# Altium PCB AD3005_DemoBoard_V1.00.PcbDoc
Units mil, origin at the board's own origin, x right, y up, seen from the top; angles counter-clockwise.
Board outline 3850.97 x 3540.97 mil, 2 copper layers (Top Layer, Bottom Layer); 155 components, 117 nets, 557 pads, 56 vias.
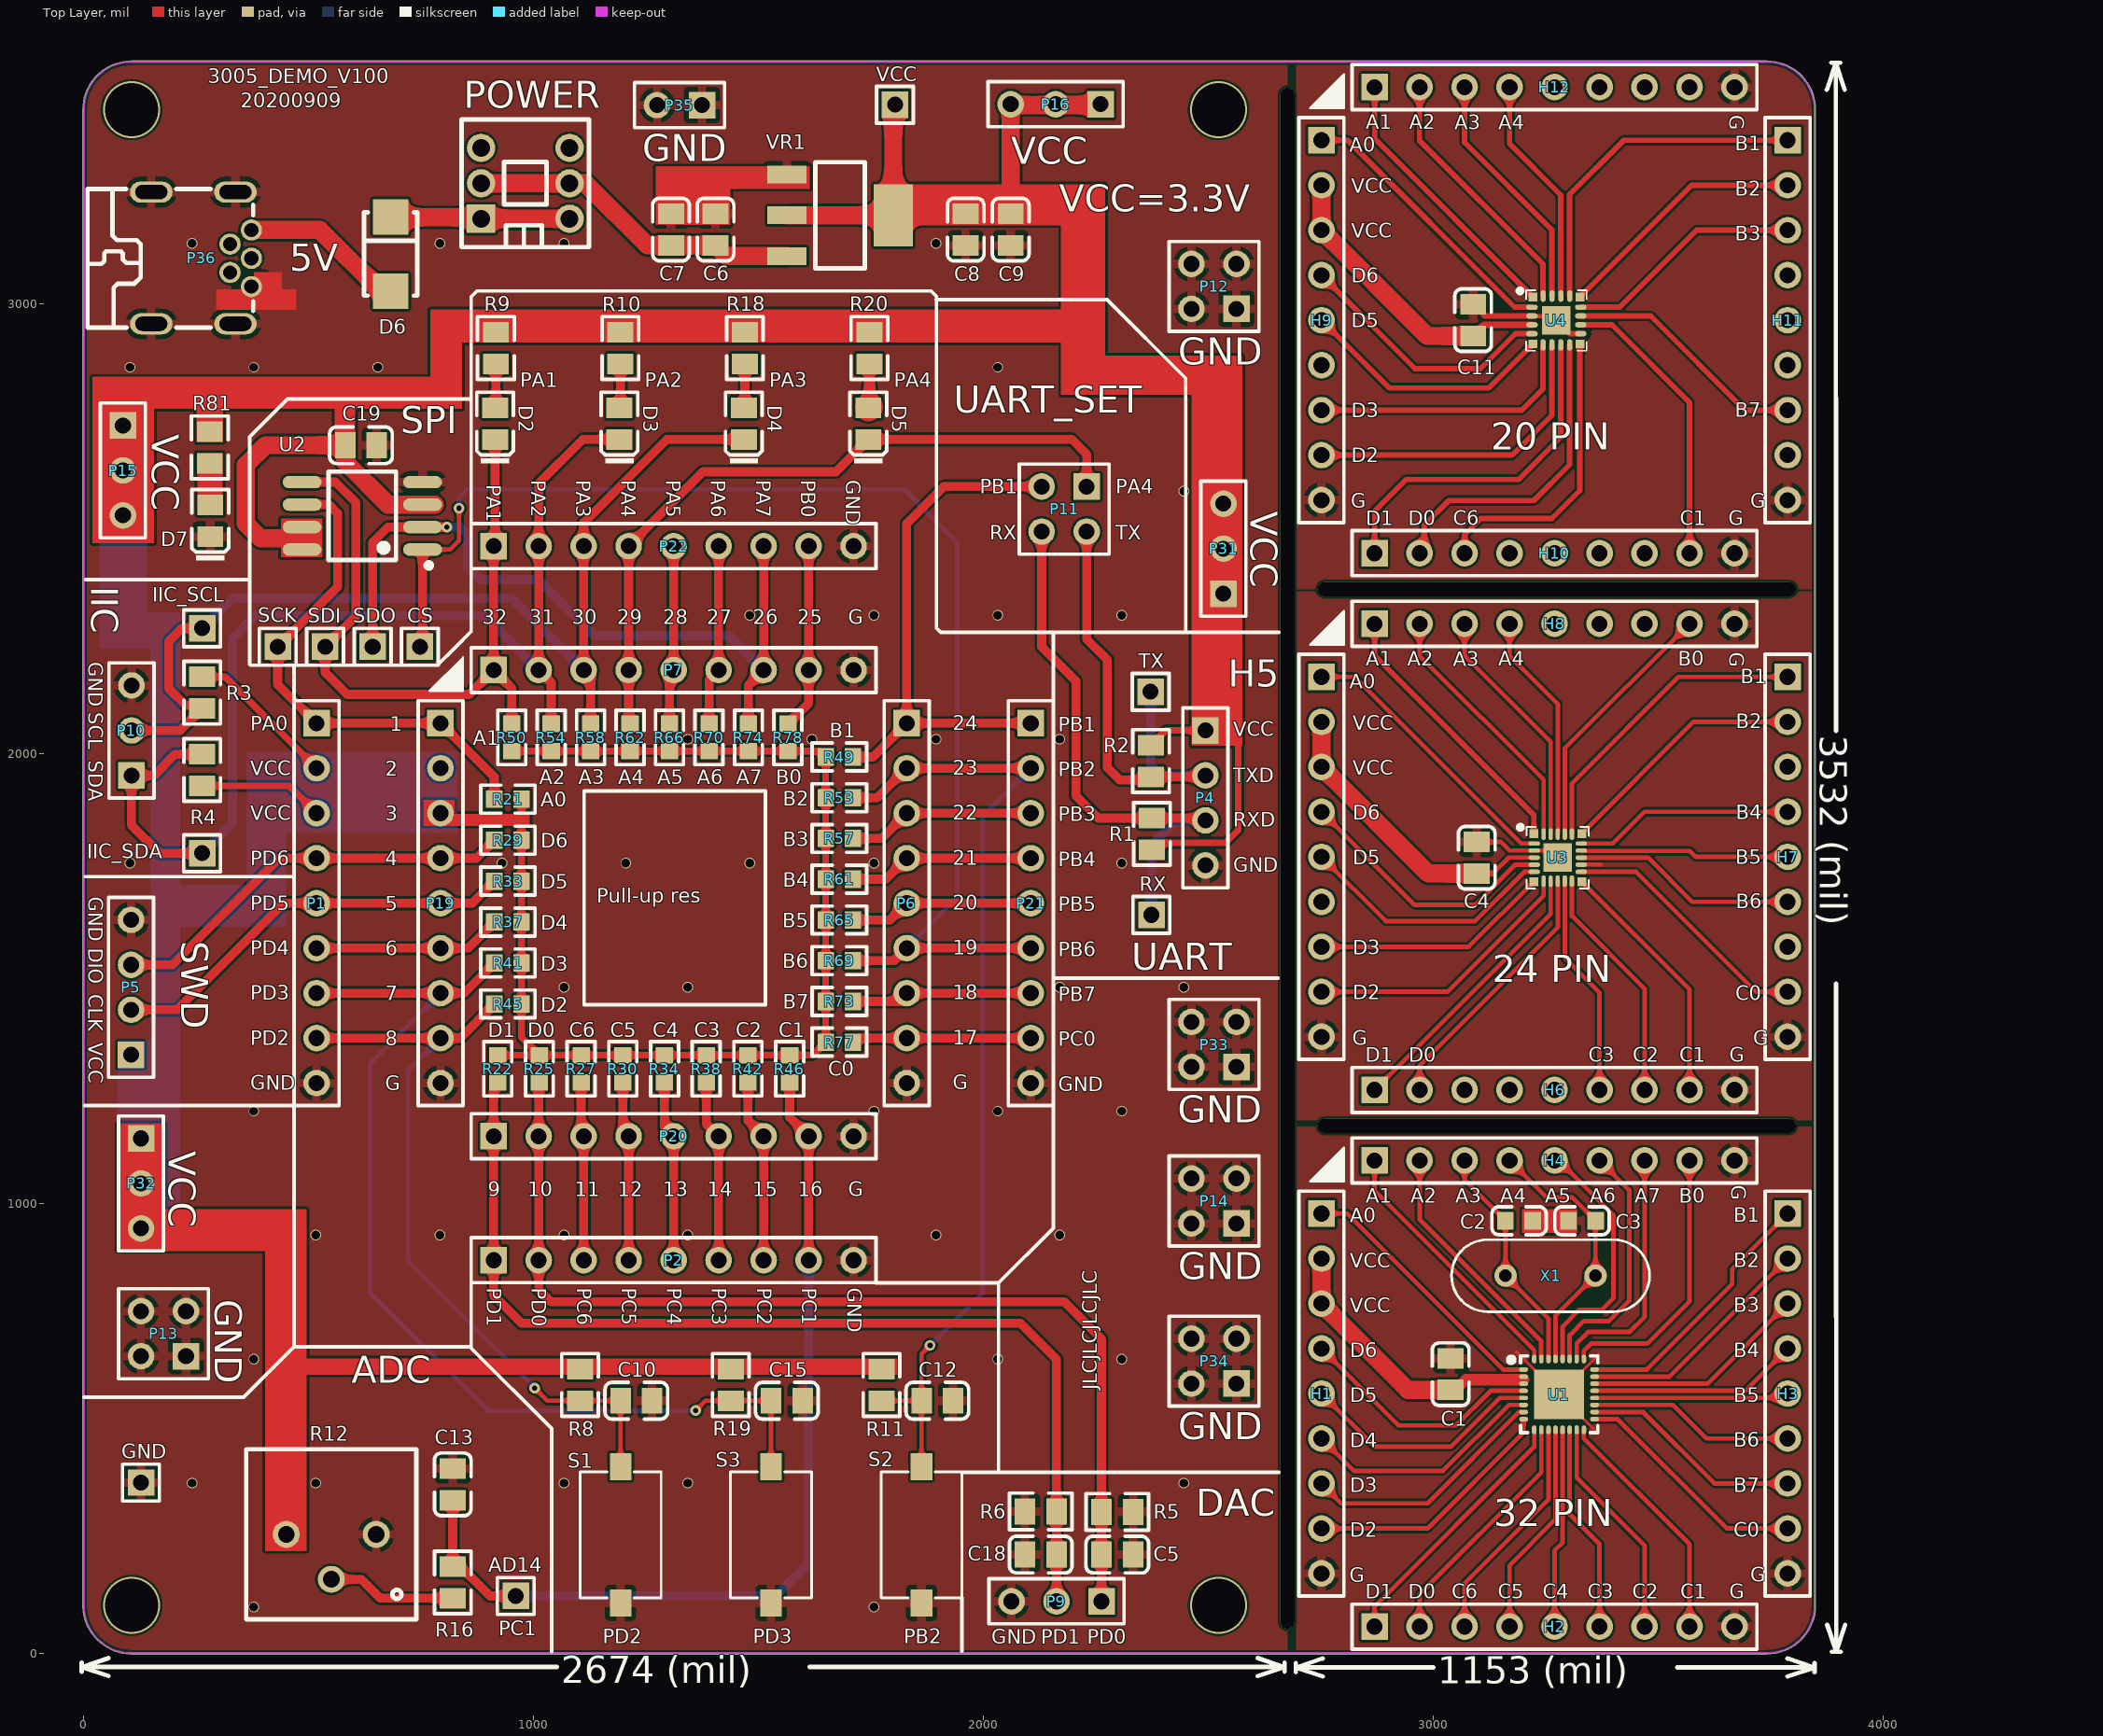
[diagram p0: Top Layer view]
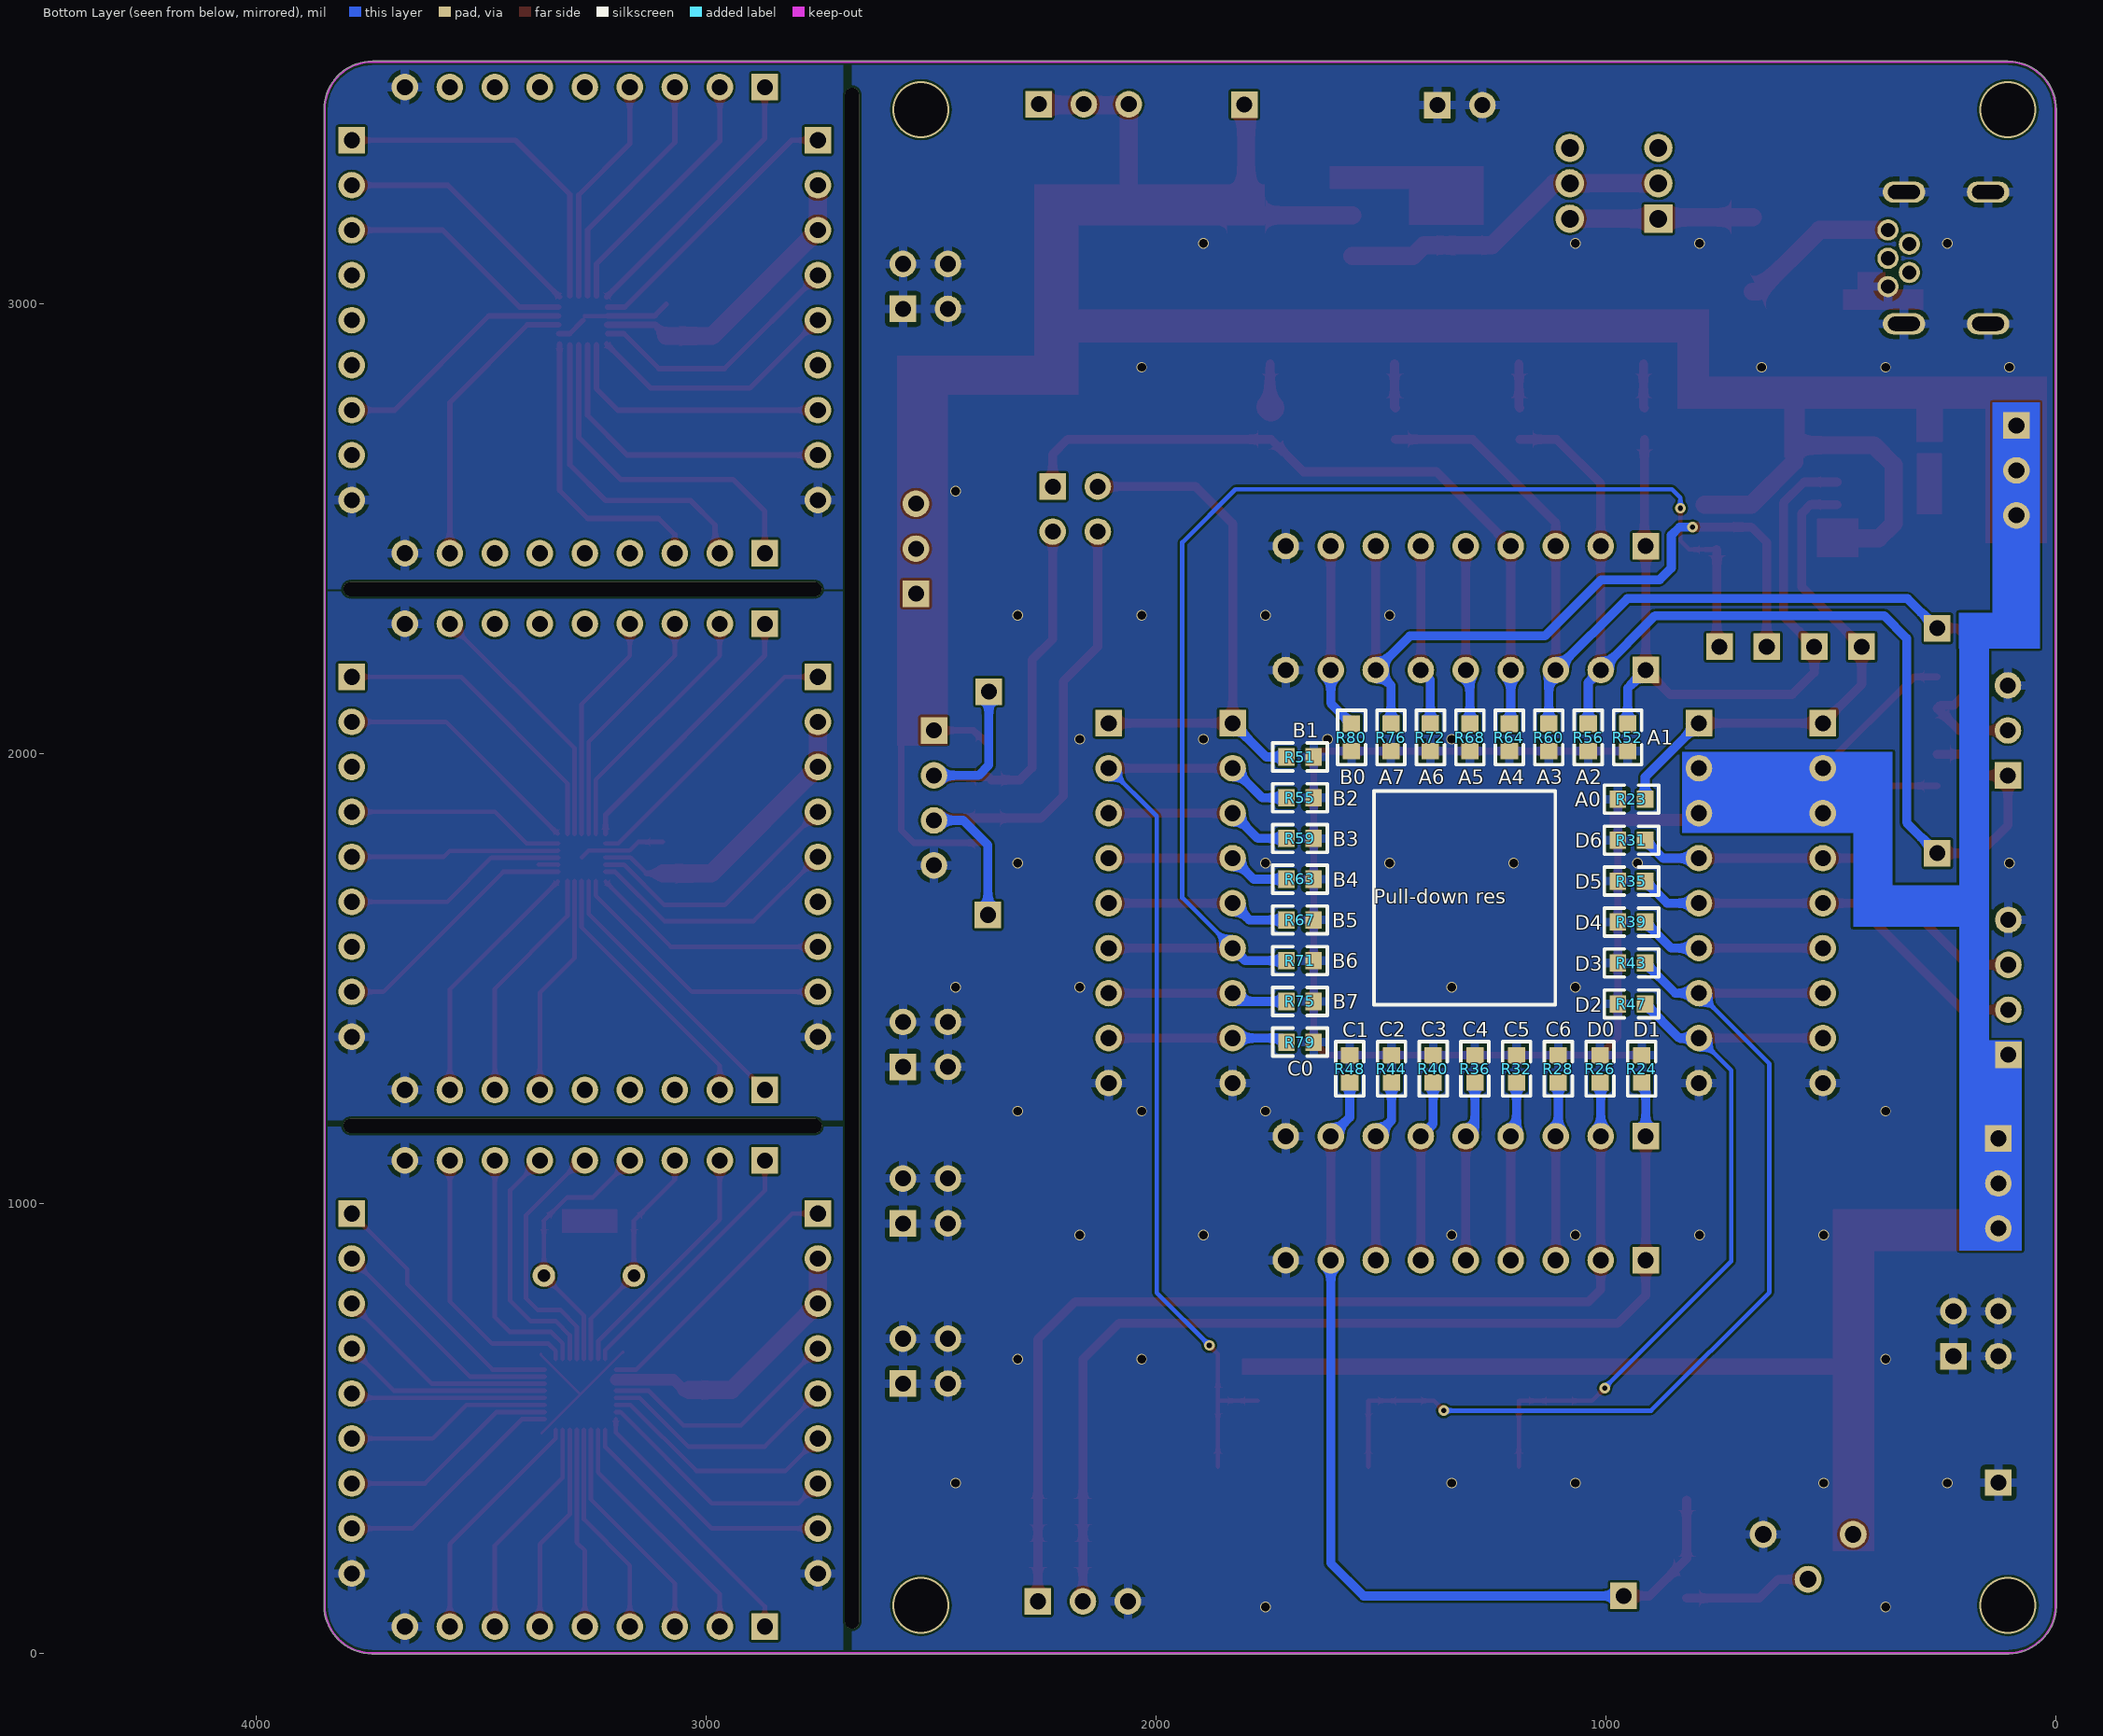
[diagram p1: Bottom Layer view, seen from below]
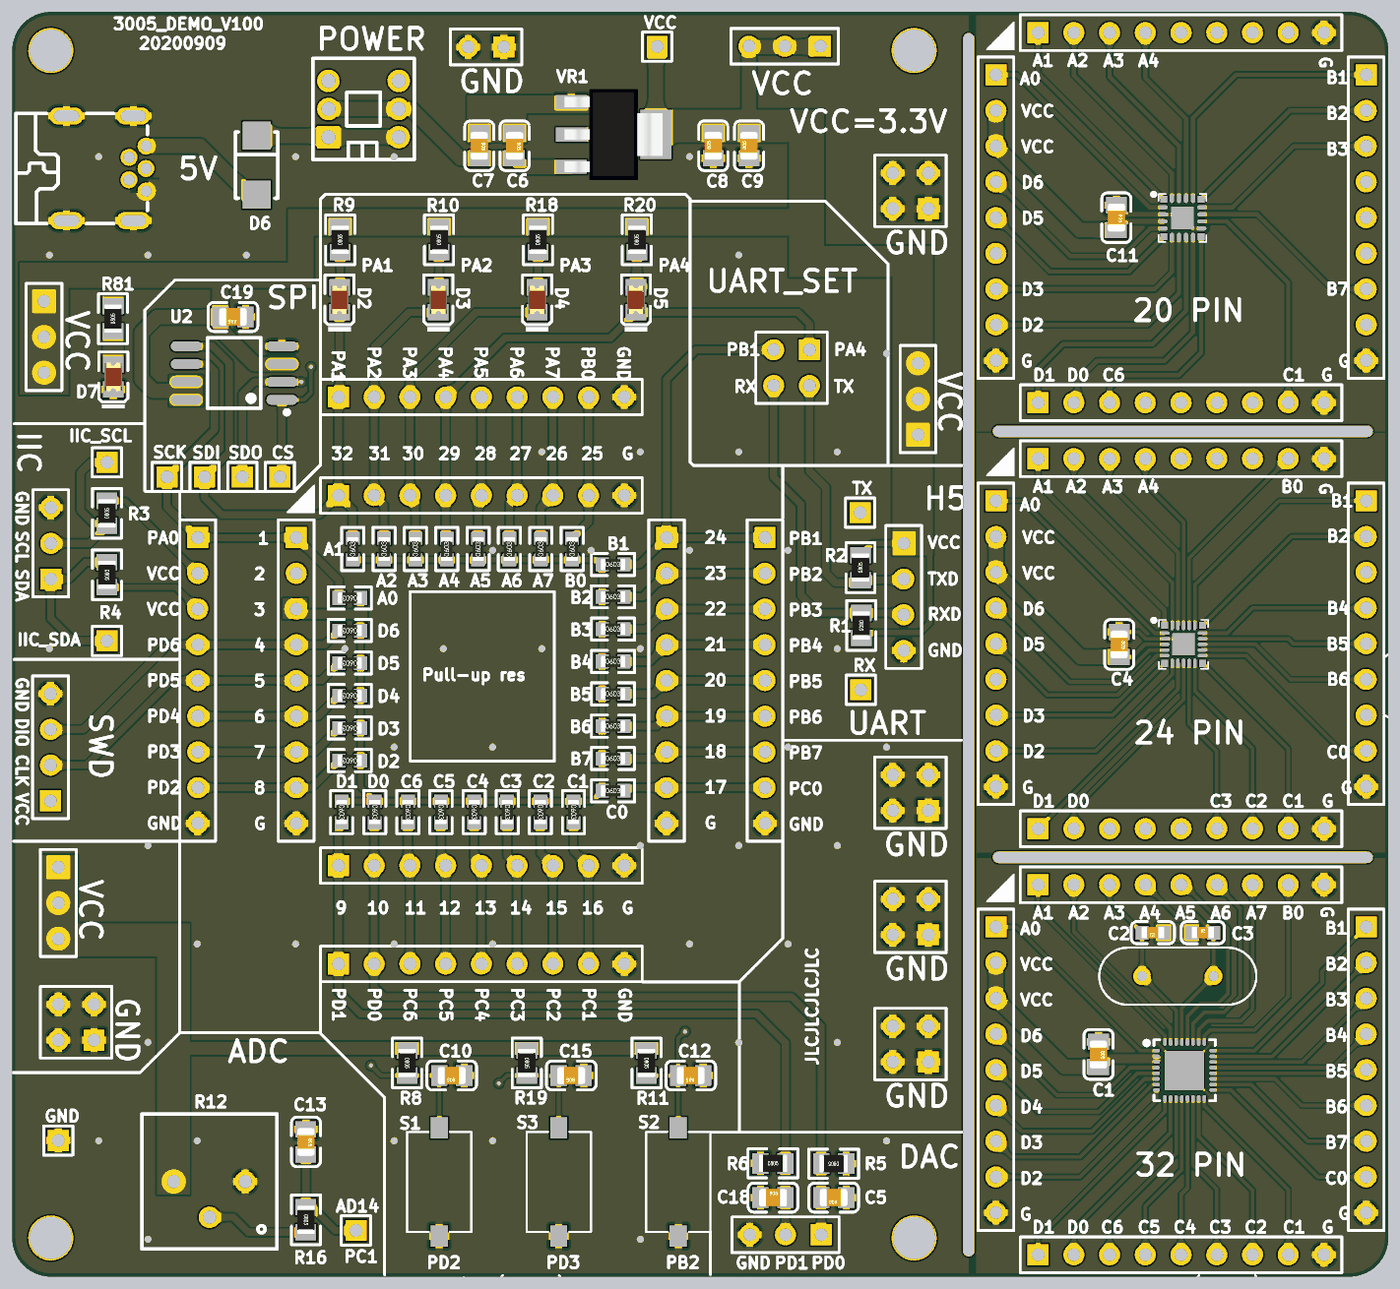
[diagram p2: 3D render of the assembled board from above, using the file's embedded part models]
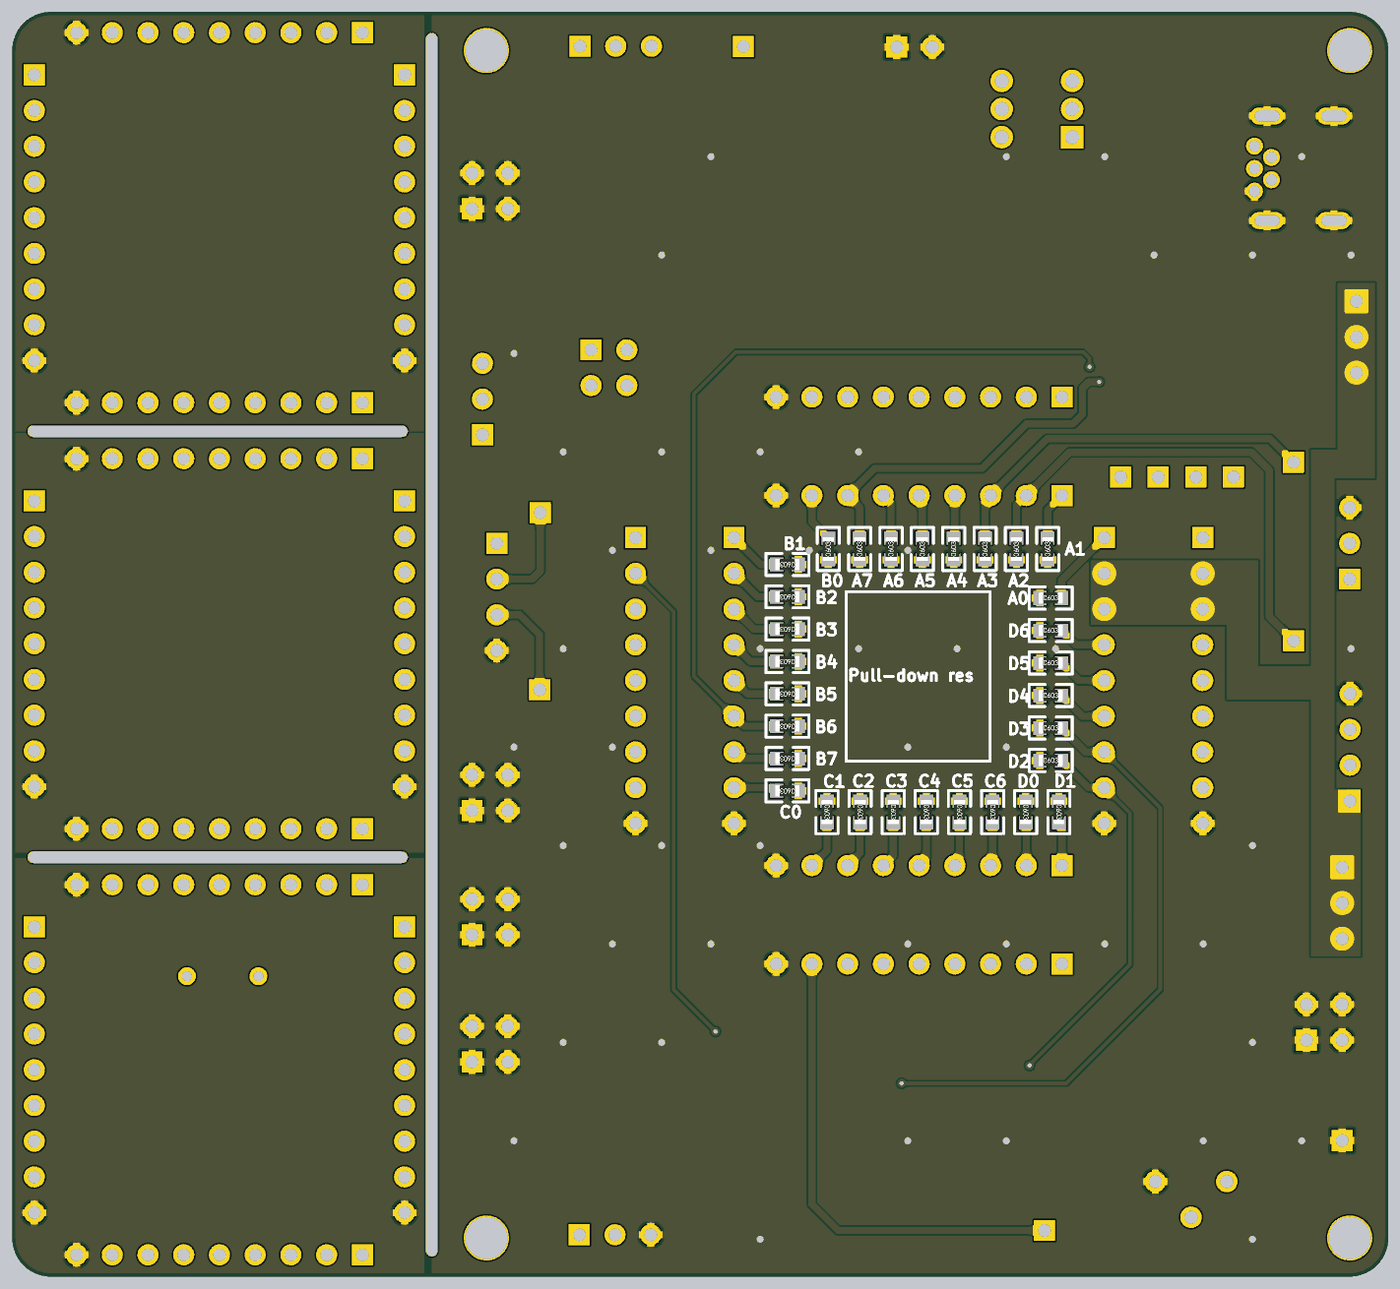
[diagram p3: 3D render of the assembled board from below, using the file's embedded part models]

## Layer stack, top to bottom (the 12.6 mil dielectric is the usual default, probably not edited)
Top Solder: solder mask 0.4, Solder Resist, Dk 3.5
Top Layer: signal copper 1.4
Dielectric 1: dielectric 12.6, FR-4, Dk 4.8
Bottom Layer: signal copper 1.4
Bottom Solder: solder mask 0.4, Solder Resist, Dk 3.5

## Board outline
103.69,-1.96 cw(c106,106) -1.96,103.69 cw(c0,104) -1.98,104 -1.98,3431 cw(c106,3431) 106,3538.98 3741,3538.98 cw(c3741,3431) 3848.98,3431 3848.98,105 cw(c3847,105) 3848.98,104.84 cw(c3741,106) 3742.16,-1.98 cw(c3742,0) 3742,-1.98 104,-1.98 cw(c104,0)

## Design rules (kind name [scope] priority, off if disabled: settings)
Clearance [All] p1: gap=5 ignorepadtopadclearanceinfootprint=FALSE
PolygonConnect PolygonConnect_1 [IsVia] p1: connectstyle=Direct reliefconductorwidth=10 reliefentries=4 polygonreliefangle="90 Angle" airgapwidth=10
PolygonConnect [All] p2: connectstyle=Relief reliefconductorwidth=20 reliefentries=4 polygonreliefangle="90 Angle" airgapwidth=10
RoutingVias [All] p1: holewidth=11.81 width=23.62 viastyle="Through Hole" minholewidth=11.81 minwidth=23.62 maxholewidth=196.85 maxwidth=236.22
SolderMaskExpansion [All] p1: expansion=4
Width [All] p1: maxlimit=80 minlimit=5 preferedwidth=15
30 further rules are at their usual default settings.

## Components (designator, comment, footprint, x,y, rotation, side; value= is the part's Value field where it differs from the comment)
AD14 "T" TEST 960,128 r90 top (schematic designator AD04)
C1 "0.1u" LC-0805_C 3038,620 r270 top
C2 "20pf" LC-0603_C 3190,961 r180 top
C3 "20pF" LC-0603_C 3330,961 r0 top
C4 "0.1u" LC-0805_C 3096,1768 r270 top
C5 "NC" LC-0805_C 2296.96,219 r180 top
C6 "10uF" LC-0805_C 1404,3164.39 r270 top
C7 "104" LC-0805_C 1305,3164.39 r270 top
C8 "10uF" LC-0805_C 1960,3164.39 r90 top
C9 "104" LC-0805_C 2060,3164.39 r90 top
C10 "104" LC-0805_C 1228,561 r180 top
C11 "0.1u" LC-0805_C 3088,2963 r270 top
C12 "104" LC-0805_C 1897,561 r180 top
C13 "104" LC-0805_C 820,375 r270 top
C15 "104" LC-0805_C 1562.5,561 r180 top
C18 "NC" LC-0805_C 2127,219 r0 top
C19 "104" LC-0805_C 616,2685 r180 top
CS "T" TEST 748,2237 r0 top
D2 "红灯 0805" LC-0805_LED_S1 914,2733 r90 top
D3 "红灯 0805" LC-0805_LED_S1 1190.56,2733 r90 top
D4 "红灯 0805" LC-0805_LED_S1 1467.11,2733 r90 top
D5 "红灯 0805" LC-0805_LED_S1 1743.67,2733 r90 top
D6 "SS34" LC-SMA(DO-214AC)_S1 682,3110 r270 top
D7 "红灯 0805" LC-0805_LED_S1 281,2517 r90 top
GND "T" TEST 128,379 r0 top
H1 "HDR-F-2.54_1x9" HDR1X9 2750.88,977 r270 top
H2 "HDR-F-2.54_1x9" HDR1X9 2869,58.91 r0 top
H3 "HDR-F-2.54_1x9" HDR1X9 3787.11,977 r270 top
H4 "HDR-F-2.54_1x9" HDR1X9 2869,1095.09 r0 top
H5 "HDR-F-2.54_1x9" HDR1X9 2750.88,2170 r270 top
H6 "HDR-F-2.54_1x9" HDR1X9 2869,1251.91 r0 top
H7 "HDR-F-2.54_1x9" HDR1X9 3787.11,2170 r270 top
H8 "HDR-F-2.54_1x9" HDR1X9 2869,2288.09 r0 top
H9 "HDR-F-2.54_1x9" HDR1X9 2750.88,3363 r270 top
H10 "HDR-F-2.54_1x9" HDR1X9 2869,2444.91 r0 top
H11 "HDR-F-2.54_1x9" HDR1X9 3787.11,3363 r270 top
H12 "HDR-F-2.54_1x9" HDR1X9 2869,3481.09 r0 top
IIC_SCL "T" TEST 263,2279 r90 top
IIC_SDA "T" TEST 264,1778 r0 top
P1 "Header 9" HDR1X9 517.29,2067 r270 top
P2 "Header 9" HDR1X9 911,873.31 r0 top
P4 "Header 4" HDR1X4 2493,2051 r270 top
P5 "Header 4" HDR1X4 105,1330 r90 top
P6 "Header 9" HDR1X9 1829.11,2067 r270 top
P7 "Header 9" HDR1X9 911,2185.09 r0 top
P9 "Header 3" HDR1X3 2262,115 r180 top
P10 "Header 3" HDR1X3 106,1951 r90 top
P11 "Header 2X2" HDR2X2 2229,2593 r180 top
P12 "Header 2X2" HDR2X2 2562,2988 r90 top
P13 "Header 2X2" HDR2X2 227,660 r90 top
P14 "Header 2X2" HDR2X2 2562,955 r90 top
P15 "Header 3" HDR1X3 87,2729 r270 top
P16 "Header 3" HDR1X3 2260,3443 r180 top
P19 "Header 9" HDR1X9 792.88,2067 r270 top
P20 "Header 9" HDR1X9 911,1148.91 r0 top
P21 "Header 9" HDR1X9 2104.7,2067 r270 top
P22 "Header 9" HDR1X9 911,2460.68 r0 top
P31 "Header 3" HDR1X3 2533,2355 r90 top
P32 "Header 3" HDR1X3 127,1144 r270 top
P33 "Header 2X2" HDR2X2 2562,1303 r90 top
P34 "Header 2X2" HDR2X2 2562,599 r90 top
P35 "Header 2" HDR1X2 1374,3441 r180 top
P36 "mini USB" PCBComponent_1 372.39,3100.5 r270 top
POWER "PB21E09471" sw 983,3269 r0 top (schematic designator SW1)
R1 "10KΩ" LC-0805_R 2374,1821 r270 top
R2 "10KΩ" LC-0805_R 2372,1983 r90 top
R3 "10KΩ" LC-0805_R 263.25,2135.04 r90 top
R4 "10KΩ" LC-0805_R 263.25,1963 r270 top
R5 "NC" LC-0805_R 2297,314 r180 top
R6 "NC" LC-0805_R 2127,315 r0 top
R8 "10KΩ" LC-0805_R 1103,596.04 r270 top
R9 "1KΩ" LC-0805_R 915.89,2901 r90 top
R10 "1KΩ" LC-0805_R 1192.59,2901 r90 top
R11 "10KΩ" LC-0805_R 1773,596.04 r270 top
R12 "R3296" WR 363.54,450.85 r0 top
R16 "1KΩ" LC-0805_R 820,157 r270 top
R18 "1KΩ" LC-0805_R 1469.3,2901 r90 top
R19 "10KΩ" LC-0805_R 1438,596.04 r270 top
R20 "1KΩ" LC-0805_R 1746,2901 r90 top
R21 "NC" LC-0603_R 942.67,1898 r180 top
R22 "NC" LC-0603_R 919.86,1298.71 r270 top
R23 "NC" LC-0603_R 942.67,1898 r180 bottom
R24 "NC" LC-0603_R 919.86,1298.71 r270 bottom
R25 "NC" LC-0603_R 1012.57,1298.71 r270 top
R26 "NC" LC-0603_R 1012.57,1298.71 r270 bottom
R27 "NC" LC-0603_R 1105.29,1298.71 r270 top
R28 "NC" LC-0603_R 1105.29,1298.71 r270 bottom
R29 "NC" LC-0603_R 942.67,1807 r180 top
R30 "NC" LC-0603_R 1198,1298.71 r270 top
R31 "NC" LC-0603_R 942.67,1807 r180 bottom
R32 "NC" LC-0603_R 1198,1298.71 r270 bottom
R33 "NC" LC-0603_R 942.67,1716 r180 top
R34 "NC" LC-0603_R 1290.71,1298.71 r270 top
R35 "NC" LC-0603_R 942.67,1716 r180 bottom
R36 "NC" LC-0603_R 1290.71,1298.71 r270 bottom
R37 "NC" LC-0603_R 942.67,1625 r180 top
R38 "NC" LC-0603_R 1383.43,1298.71 r270 top
R39 "NC" LC-0603_R 942.67,1625 r180 bottom
R40 "NC" LC-0603_R 1383.43,1298.71 r270 bottom
R41 "NC" LC-0603_R 942.67,1534 r180 top
R42 "NC" LC-0603_R 1476.14,1298.71 r270 top
R43 "NC" LC-0603_R 942.67,1534 r180 bottom
R44 "NC" LC-0603_R 1476.14,1298.71 r270 bottom
R45 "NC" LC-0603_R 942.67,1443 r180 top
R46 "NC" LC-0603_R 1568.86,1298.71 r270 top
R47 "NC" LC-0603_R 942.67,1443 r180 bottom
R48 "NC" LC-0603_R 1568.86,1298.71 r270 bottom
R49 "NC" LC-0603_R 1679.32,1992 r0 top
R50 "NC" LC-0603_R 951,2035.31 r90 top
R51 "NC" LC-0603_R 1679.32,1992 r0 bottom
R52 "NC" LC-0603_R 951,2035.31 r90 bottom
R53 "NC" LC-0603_R 1679.32,1901.43 r0 top
R54 "NC" LC-0603_R 1038.71,2035.31 r90 top
R55 "NC" LC-0603_R 1679.32,1901.43 r0 bottom
R56 "NC" LC-0603_R 1038.71,2035.31 r90 bottom
R57 "NC" LC-0603_R 1679.32,1810.86 r0 top
R58 "NC" LC-0603_R 1126.43,2035.31 r90 top
R59 "NC" LC-0603_R 1679.32,1810.86 r0 bottom
R60 "NC" LC-0603_R 1126.43,2035.31 r90 bottom
R61 "NC" LC-0603_R 1679.32,1720.29 r0 top
R62 "NC" LC-0603_R 1214.14,2035.31 r90 top
R63 "NC" LC-0603_R 1679.32,1720.29 r0 bottom
R64 "NC" LC-0603_R 1214.14,2035.31 r90 bottom
R65 "NC" LC-0603_R 1679.32,1629.71 r0 top
R66 "NC" LC-0603_R 1301.86,2035.31 r90 top
R67 "NC" LC-0603_R 1679.32,1629.71 r0 bottom
R68 "NC" LC-0603_R 1301.86,2035.31 r90 bottom
R69 "NC" LC-0603_R 1679.32,1539.14 r0 top
R70 "NC" LC-0603_R 1389.57,2035.31 r90 top
R71 "NC" LC-0603_R 1679.32,1539.14 r0 bottom
R72 "NC" LC-0603_R 1389.57,2035.31 r90 bottom
R73 "NC" LC-0603_R 1679.32,1448.57 r0 top
R74 "NC" LC-0603_R 1477.29,2035.31 r90 top
R75 "NC" LC-0603_R 1679.32,1448.57 r0 bottom
R76 "NC" LC-0603_R 1477.29,2035.31 r90 bottom
R77 "NC" LC-0603_R 1679.32,1358 r0 top
R78 "NC" LC-0603_R 1565,2035.31 r90 top
R79 "NC" LC-0603_R 1679.32,1358 r0 bottom
R80 "NC" LC-0603_R 1565,2035.31 r90 bottom
R81 "1KΩ" LC-0805_R 280,2680 r90 top
RX "T" TEST 2374,1641 r0 top
S1 "SW-PB" SW_A0306 1193,263 r270 top
S2 "SW-PB" SW_A0306 1862,263 r270 top
S3 "SW-PB" SW_A0306 1527.5,263 r270 top
SCK "T" TEST 432,2237 r0 top
SDI "T" TEST 537.33,2237 r0 top
SDO "T" TEST 643,2237 r0 top
TX "T" TEST 2372,2137 r0 top
U1 "AD3005_Q32" QFN32 3200.24,653.89 r270 top
U2 "W25Q128FVSIG" LC-SOIC-8_208mil 619,2528 r90 top
U3 "AD3005_Q24" QFN24 3216.89,1827.66 r270 top
U4 "AD3005_Q20_B" QFN20 3214.19,3021.13 r270 top
VCC "T" TEST 1804,3442 r0 top
VR1 "AMS1117-3.3" LC-SOT-223 1681,3196 r180 top
X1 "8MHz" CRY3 3360.41,838.84 r180 top

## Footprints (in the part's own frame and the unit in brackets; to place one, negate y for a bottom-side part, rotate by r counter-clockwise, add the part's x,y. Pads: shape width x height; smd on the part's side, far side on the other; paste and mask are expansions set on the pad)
CRY3 [mil]
  round 50 hole 28: 1(200.41,-0.16) 2(0.41,-0.16)
  silkscreen extent -120,-80 320,80
HDR1X2 [mm] "Connector; Header; 2 Position"
  rect 1.5x1.5 hole 0.9: 1(0,0)
  round 1.5 hole 0.9: 2(2.54,0)
  silkscreen extent -1.27,-1.27 3.81,1.27
HDR1X3 [mm] "Connector; Header; 3 Position"
  rect 1.5x1.5 hole 0.9: 1(0,0)
  round 1.5 hole 0.9: 2(2.54,0) 3(5.08,0)
  silkscreen extent -1.27,-1.27 6.35,1.27
HDR1X4 [mm] "Connector; Header; 4 Position"
  rect 1.5x1.5 hole 0.9: 1(0,0)
  round 1.5 hole 0.9: 2(2.54,0) 3(5.08,0) 4(7.62,0)
  silkscreen extent -1.27,-1.27 8.89,1.27
HDR1X9 [mm] "Connector; Header; 9 Position"
  rect 1.5x1.5 hole 0.9: 1(0,0)
  round 1.5 hole 0.9: 2(2.54,0) 3(5.08,0) 4(7.62,0) 5(10.16,0) 6(12.7,0) 7(15.24,0) 8(17.78,0) 9(20.32,0)
  silkscreen extent -1.27,-1.27 21.59,1.27
HDR2X2 [mm] "Connector; Header; 2x2 Position"
  rect 1.5x1.5 hole 0.9: 1(0,0)
  round 1.5 hole 0.9: 2(0,2.54) 3(2.54,0) 4(2.54,2.54)
  silkscreen extent -1.27,-1.27 3.81,3.81
LC-0603_C [mm]
  rect 0.93x0.98 smd: 1(-0.77,0) 2(0.77,0)
  silkscreen extent -1.53,-0.79 1.54,0.79, body extent -0.8,-0.4 0.8,0.4, height 0.3
LC-0603_R [mm]
  rect 0.93x0.98 smd: 1(-0.77,0) 2(0.77,0)
  silkscreen extent -1.53,-0.79 1.54,0.79, body extent -0.85,-0.4 0.85,0.4, height 0.56
LC-0805_C [mm]
  rect 1.16x1.47 smd: 1(-0.89,0) 2(0.89,0)
  silkscreen extent -1.77,-1.04 1.77,1.04, body extent -1,-0.62 1,0.63, height 0.77
LC-0805_LED_S1 [mm]
  rect 1.16x1.47 smd: A(0.89,0) K(-0.89,0)
  silkscreen extent -2.25,-1.03 1.77,1.03, body extent -1.01,-0.62 1.01,0.62, height 1.1
LC-0805_R [mm]
  rect 1.16x1.47 smd: 1(-0.89,0) 2(0.89,0)
  silkscreen extent -1.77,-1.03 1.77,1.03, body extent -1,-0.62 1,0.63, height 0.49
LC-SMA(DO-214AC)_S1 [mm]
  rect 2x2 smd: 1(2.1,0) 2(-2.1,0)
  silkscreen extent -2.35,-1.5 2.35,1.5
LC-SOIC-8_208mil [mm]
  oval 0.7x2.2 smd: 1(-1.905,-3.4) 2(-0.635,-3.4) 3(0.635,-3.4) 4(1.905,-3.4) 5(1.905,3.4) 6(0.635,3.4) 7(-0.635,3.4) 8(-1.905,3.4)
  silkscreen extent -2.95,-3.9 2.5,1.9
LC-SOT-223 [mm]
  rect 2.2x1 smd: 1(3,-2.3) 2(3,0) 3(3,2.3)
  rect 2.2x3.5 smd: 2(-3,0)
  silkscreen extent -1.4,-3 1.4,3, body extent -3.49,-3.24 3.49,3.24, height 1.64
PCBComponent_1 [mm]
  oval 1.2x2.4 hole 0.8 slot 1.8 at 90 deg: 0(-3.74,-0.902) 0(-3.74,-5.652) 0(3.7,-0.902) 0(3.7,-5.652)
  round 1.2 hole 0.8: 1(-1.6,0) 2(-0.8,-1.204) 3(0,0) 4(0.8,-1.204) 5(1.6,0)
  silkscreen extent -3.91,-9.25 3.91,0.1
QFN20 [mm]
  rect 0.5x0.5 smd mask+0.051: 1(0.167,0.167) 6(2.819,0.167) 11(2.819,2.819) 16(0.167,2.819)
  oval 0.3x0.65 smd mask+0.051: 2(0.743,0.117) 3(1.243,0.117) 4(1.743,0.117) 5(2.243,0.117) 12(2.243,2.87) 13(1.743,2.87) 14(1.243,2.87) 15(0.743,2.87)
  oval 0.65x0.3 smd mask+0.051: 7(2.87,0.744) 8(2.87,1.244) 9(2.87,1.744) 10(2.87,2.244) 17(0.116,2.244) 18(0.116,1.744) 19(0.116,1.244) 20(0.116,0.744)
  rect 1.6x1.6 smd mask+0.051: 21(1.493,1.494)
  silkscreen extent -0.3,-0.69 3.2,3.2
QFN24 [mm]
  rect 0.5x0.5 smd mask+0.051: 1(0.159,0.152) 7(2.863,0.152) 13(2.863,2.856) 19(0.159,2.856)
  oval 0.25x0.65 smd mask+0.051: 2(0.711,0.178) 3(1.111,0.178) 4(1.511,0.178) 5(1.911,0.178) 6(2.311,0.178) 14(2.311,2.83) 15(1.911,2.83) 16(1.511,2.83) 17(1.111,2.83) 18(0.711,2.83)
  oval 0.65x0.25 smd mask+0.051: 8(2.837,0.704) 9(2.837,1.104) 10(2.837,1.504) 11(2.837,1.904) 12(2.837,2.304) 20(0.185,2.304) 21(0.185,1.904) 22(0.185,1.504) 23(0.185,1.104) 24(0.185,0.704)
  rect 1.6x1.6 smd mask+0.051: 25(1.499,1.499)
  silkscreen extent -0.33,-0.74 3.25,3.25
QFN32 [mm]
  oval 0.26x0.5 smd mask+0.051: 1(0.6,0) 2(1,0) 3(1.4,0) 4(1.8,0) 5(2.2,0) 6(2.6,0) 7(3,0) 8(3.4,0) 17(3.4,4) 18(3,4) 19(2.6,4) 20(2.2,4) 21(1.8,4) 22(1.4,4) 23(1,4) 24(0.6,4)
  oval 0.5x0.26 smd mask+0.051: 9(4.004,0.6) 10(4.004,1) 11(4.004,1.4) 12(4.004,1.8) 13(4.004,2.2) 14(4.004,2.6) 15(4.004,3) 16(4.004,3.4) 25(0.004,3.4) 26(0.004,3) 27(0.004,2.6) 28(0.004,2.2) 29(0.004,1.8) 30(0.004,1.4) 31(0.004,1) 32(0.004,0.6)
  rect 2.8x2.8 smd mask+0.051: 33(2.004,2)
  silkscreen extent -0.18,-0.85 4.16,4.18
sw [mm]
  rect 1.6x1.6 hole 1: 1(-2.543,-2.045)
  round 1.6 hole 1: 2(-2.543,-0.045) 3(-2.543,1.955) 4(2.457,-2.045) 5(2.457,-0.045) 6(2.457,1.955)
  silkscreen extent -3.64,-3.64 3.56,3.55
SW_A0306 [mil] "SW_A0306"
  rect 60x48 smd: 1(-151.57,0) 2(151.57,0)
  silkscreen extent -140,-90 140,90
TEST [mm]
  rect 1.5x1.5 hole 0.9: 1(-0.025,0)
  silkscreen extent -1.07,-1.04 1.02,1.04
WR [mil]
  round 60 hole 37: 1(86.46,-186.85) 2(186.46,-286.85) 3(286.46,-186.85)
  silkscreen extent -3,-376 375,2

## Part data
AD14 CS GND IIC_SCL IIC_SDA RX SCK SDI SDO TX VCC: library part TEST
C3: library part 20pf
C5 C6 C7 C8 C9 C10 C12 C13 C15 C18 C19: library part "0805 100nF(104) 10% 50V", "贴片电容", Package=0805, SuppliersPartNumber=C49678
D2 D3 D4 D5 D7: library part "0805 红灯", "发光二极管", Package=0805, SuppliersPartNumber=C2295
D6: library part "SMA(DO-214AC) SS54", "二极管", Package=SMA(DO-214AC), SuppliersPartNumber=C22452
P1 P2 P6 P7 P19 P20 P21 P22: "Header, 9-Pin"
P4 P5: "Header, 4-Pin"
P9 P10 P15 P16 P31 P32: "Header, 3-Pin"
P11 P12 P13 P14 P33 P34: "Header, 2-Pin, Dual row"
P35: "Header, 2-Pin"
P36: library part "Header 5", "Header, 5-Pin"
POWER: BOM_Manufacturer=GANGYUAN
R1 R2 R3 R4 R5 R6 R8 R11 R19: library part "0805 10KΩ (1002) 1%", "贴片电阻", Package=0805, SuppliersPartNumber=C17414
R9 R10 R16 R18 R20 R81: library part "0805 1KΩ (1001) 1%", "贴片电阻", Package=0805, SuppliersPartNumber=C17513
R21 R22 R23 R24 R25 R26 R27 R28 R29 R30 R31 R32 R33 R34 R35 R36 R37 R38 R39 R40 R41 R42 R43 R44 R45 R46 R47 R48 R49 R50 R51 R52 R53 R54 R55 R56 R57 R58 R59 R60 R61 R62 R63 R64 R65 R66 R67 R68 R69 R70 R71 R72 R73 R74 R75 R76 R77 R78 R79 R80: library part "0603 0Ω (0R0) 1%", "贴片电阻", Package=0603, SuppliersPartNumber=C21189
S1 S2 S3: "Switch"
U2: "Flash ROM", Package=SOIC-8, SuppliersPartNumber=C35101
VR1: library part "SOT-223 AMS1117-5.0", "低压差线性稳压(LDO)", Package=SOT-223, SuppliersPartNumber=C6187
X1: BOM_Manufacturer=TAE, BOM_Manufacturer Part=HC-49S25MHz20pF30PPM

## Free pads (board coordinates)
  oval 31.5x3425.2 hole 31.5 slot 3425.2 at 90 deg: 1(2675,1767)
  oval 1062.99x31.5 hole 31.5 slot 1062.99 at 0 deg: 1(3274,1172) 1(3274,2365)

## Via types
v1: diameter 23.62, hole 19.68, Top Layer to Bottom Layer, tented both sides, 47 vias
v2: diameter 23.62, hole 11.81, Top Layer to Bottom Layer, tented both sides, 5 vias
v3: diameter 125.98, hole 118.11, Top Layer to Bottom Layer, 4 vias

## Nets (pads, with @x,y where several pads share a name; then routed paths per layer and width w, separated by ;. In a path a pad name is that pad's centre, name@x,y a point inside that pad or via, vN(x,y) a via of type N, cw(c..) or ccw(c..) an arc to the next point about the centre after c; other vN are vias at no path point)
GND: C5.1 C6.1 C7.1 C8.1 C9.1 C10.1 C12.1 C13.1 C15.1 C18.1 C19.1 D7.K GND.1 P1.9 P2.9 P4.4 P5.4 P6.9 P7.9 P9.3 P10.3 P12.1 P12.2 P12.3 P12.4 P13.1 P13.2 P13.3 P13.4 P14.1 P14.2 P14.3 P14.4 P19.9 P20.9 P21.9 P22.9 P33.1 P33.2 P33.3 P33.4 P34.1 P34.2 P34.3 P34.4 P35.1 P35.2 P36.0 P36.5 R5.1 R6.1 R12.3 R23.1 R24.1 R26.1 R28.1 R31.1 R32.1 R35.1 R36.1 R39.1 R40.1 R43.1 R44.1 R47.1 R48.1 R51.1 R52.1 R55.1 R56.1 R59.1 R60.1 R63.1 R64.1 R67.1 R68.1 R71.1 R72.1 R75.1 R76.1 R79.1 R80.1 S1.2 S2.2 S3.2 U2.4 VR1.1
  other v1: 377.95,102.36 1755.91,102.36 240.16,377.95 515.75,377.95 1066.93,377.95 1342.52,377.95 2444.88,377.95 377.95,653.54 2031.5,653.54 2307.09,653.54 515.75,929.13 791.34,929.13 1066.93,929.13 1342.52,929.13 1893.7,929.13 2169.29,929.13 377.95,1204.72 1755.91,1204.72 2031.5,1204.72 2307.09,1204.72 1066.93,1480.32 1342.52,1480.32 2169.29,1480.32 2444.88,1480.32 102.36,1755.91 929.13,1755.91 1204.72,1755.91 1480.32,1755.91 1755.91,1755.91 2307.09,1755.91 1342.52,2031.5 1618.11,2031.5 1893.7,2031.5 2169.29,2031.5 1480.32,2307.09 1755.91,2307.09 2031.5,2307.09 2307.09,2307.09 2444.88,2582.68 102.36,2858.27 377.95,2858.27 653.54,2858.27 2031.5,2858.27 240.16,3133.86 791.34,3133.86 1066.93,3133.86 1893.7,3133.86
GND_20: C11.1 H9.9 H10.9 H11.9 H12.9 U4.3 U4.12 U4.21 | length 207.9
  Top Layer w12: C11.1 3113.85,2972.19 U4.3 ; U4.21 3302.52,2932.82 U4.12
GND_24: C4.1 H5.9 H6.9 H7.9 H8.9 U3.3 U3.15 U3.25 | length 238.1
  Top Layer w10: C4.1 3149.96,1803.04 3169.09,1783.91 U3.3 3260.64,1783.91 U3.25 ; U3.15 3328.9,1753 3372,1753
GND_32: C1.1 C2.1 C3.1 H1.9 H2.9 H3.9 H4.9 U1.33 | length 383.4
  Top Layer w6: 3183,668 3184,669 3184,670 U1.33@3277.99,576.01 ; 3365,489 U1.33 3367,663 3367,665
HVCC: D6.2 POWER.1 POWER.4 | length 408
  Top Layer w40: D6.2@673,3191.68 879.7,3191.68 POWER.1 POWER.4
NetD2_A: D2.A R9.1 | length 98.7
  Top Layer w20: D2.A 915.89,2769.93 R9.1
NetD3_A: D3.A R10.1 | length 98.8
  Top Layer w20: D3.A 1192.59,2770.08 R10.1
NetD4_A: D4.A R18.1 | length 98.8
  Top Layer w20: D4.A 1469.3,2770.23 R18.1
NetD5_A: D5.A R20.1 | length 98.9
  Top Layer w20: D5.A@1746,2770.37 R20.1
  Top Layer w60: D5.A D5.A@1746,2770.37
NetD6_1: D6.1 P36.1 | length 357.4
  Top Layer w40: P36.1 524.51,3163.49 661.68,3026.32 D6.1@673,3026.32
NetD7_A: D7.A R81.1
NetR12_2: R12.2 R16.2 | length 287.4
  Top Layer w20: R12.2 617,164 659.04,121.96 R16.2
PA0: P1.1 P19.1 R21.2 R23.2 SCK.1 U2.6 | length 1357.1
  Top Layer w20: U2.6 545,2553 564,2534 564,2370 SCK.1 431,2153.29 P1.1 P19.1 912.35,1947.53 R21.2
  Bottom Layer w20: P19.1 912.35,1947.53 R23.2
PA0_20: H9.1 U4.2 | length 621.6
  Top Layer w12: H9.1 2809,3363 3180.13,2991.87 U4.2
PA0_24: H5.1 U3.2 | length 626.4
  Top Layer w10: H5.1 2825,2170 3195.34,1799.66 U3.2
PA0_32: H1.1 U1.1 | length 593
  Top Layer w10: H1.1 2808,977 3154.71,630.29 U1.1
PA1: D2.K P7.1 P22.1 R50.2 R52.2 SDI.1 U2.5 | length 1748.1
  Top Layer w20: U2.5 559,2603 605,2557 605,2305.67 SDI.1 536.33,2179.67 585,2131 856.91,2131 P7.1 ; D2.K 914,2463.68 P22.1 P7.1 ; R50.2 951,2145.09 P7.1
  Bottom Layer w20: P7.1 951,2145.09 R52.2
PA1_20: H12.1 U4.1 | length 612.3
  Top Layer w12: H12.1 2869,3366.34 U4.1
PA1_24: H8.1 U3.1 | length 613.3
  Top Layer w12: H8.1 2869,2217 3222.88,1863.12 U3.1
PA1_32: H4.1 U1.32 | length 588.3
  Top Layer w10: H4.1 2869,1028 3223.87,673.13 U1.32
PA2: D3.K IIC_SDA.1 P7.2 P10.1 P22.2 R4.1 R54.2 R56.2 | length 2624.3
  Top Layer w20: IIC_SDA.1 168,1778 106,1840 P10.1 156,1951 203.04,1998.04 R4.1 ; R54.2 1038.71,2157.38 P7.2 P22.2 1011,2600 1108.96,2697.96 D3.K
  Bottom Layer w20: IIC_SDA.1 331,1846 331,2256 381,2306 890.09,2306 P7.2 1038.71,2157.38 R56.2
PA2_20: H12.2 U4.20 | length 578.2
  Top Layer w12: H12.2 2969,3362 3243.47,3087.53 U4.20
PA2_24: H8.2 U3.24 | length 581.9
  Top Layer w10: H8.2 2969,2217 3244.61,1941.39 U3.24
PA2_32: H4.2 U1.31 | length 553.4
  Top Layer w10: H4.2 2969,964 3238.98,694.02 3238.98,654.37 U1.31
PA3: D4.K IIC_SCL.1 P7.3 P10.2 P22.3 R3.1 R58.2 R60.2 | length 2414.6
  Top Layer w20: P10.2 214.25,2051 R3.1 256.25,2107 226,2107 189,2144 189,2249 218,2278 IIC_SCL.1 ; R58.2 1126.43,2169.66 P7.3 P22.3 1111,2513 1295.96,2697.96 D4.K
  Bottom Layer w20: IIC_SCL.1 329,2344 952.09,2344 P7.3 1126.43,2169.66 R60.2
PA3_20: H12.3 U4.19 | length 545
  Top Layer w12: H12.3 3069,3358 3263.15,3163.85 U4.19
PA3_24: H8.3 U3.23 | length 547
  Top Layer w10: H8.3 3069,2217 3260.35,2025.65 U3.23
PA3_32: C2.2 H4.3 U1.30 X1.1 | length 518.6
  Top Layer w10: H4.3 3069,1051.68 C2.2 3160,960.68 X1.1 3255.36,743.64 U1.30
PA4: D5.K P7.4 P11.1 P22.4 R62.2 R64.2 | length 1719.1
  Top Layer w20: R62.2 1211,2068.77 P7.4 P22.4 1376.32,2626 1671.71,2626 D5.K 2196.04,2697.96 2229,2665 P11.1
  Bottom Layer w20: P7.4 1211,2068.77 R64.2
PA4_20: H12.4 U4.18 | length 511.7
  Top Layer w12: H12.4 3169,3355 3282.84,3241.16 U4.18
PA4_24: H8.4 U3.22 | length 512.1
  Top Layer w10: H8.4 3169,2217 3276.1,2109.9 U3.22
PA4_32: C3.2 H4.4 U1.29 X1.2 | length 591.1
  Top Layer w10: H4.4 3251.09,1013 3308.31,1013 C3.2 3360,960.68 X1.2 3271.11,750.11 U1.29
PA4_TX: P4.2 P11.2 R2.1 TX.1 | length 1071.9
  Top Layer w20: P11.2 2229,2254 2275,2208 2275,1968 2302,1941 2365.04,1941 R2.1 2489.96,1947.96 P4.2
  Bottom Layer w20: TX.1 2371,1974 2394,1951 P4.2
PA5: P7.5 P22.5 R66.2 R68.2 | length 522.1
  Top Layer w20: R66.2 1301.86,2175.95 P7.5 P22.5
  Bottom Layer w20: R68.2 1301.86,2175.95 P7.5
PA5_32: H4.5 U1.28 | length 577
  Top Layer w10: H4.5 3277.96,1095.09 3400,973.06 3400,789 3374,763 3324,763 3286.86,725.86 U1.28
PA6: P7.6 P22.6 R70.2 R72.2 | length 532.3
  Top Layer w20: R70.2 1389.57,2163.67 P7.6 P22.6
  Bottom Layer w20: R72.2 1389.57,2163.67 P7.6
PA6_32: H4.6 U1.27 | length 556.3
  Top Layer w10: U1.27 3302.61,706.61 3334,738 3390,738 3435,783 3435,1029.09 H4.6
PA7: P7.7 P22.7 R74.2 R76.2 SDO.1 U2.2 | length 1832
  Top Layer w20: SDO.1 642,2469 676,2503 U2.2 v2(807,2503) ; R74.2 1477.29,2151.38 P7.7 P22.7
  Bottom Layer w20: v2(807,2503) 836,2503 854,2485 854,2412 880,2386 1010,2386 1135,2261 1435.09,2261 P7.7 1477.29,2151.38 R76.2
PA7_32: H4.7 U1.26 | length 557.6
  Top Layer w10: U1.26 3318.35,688.35 3344,714 3436,714 3469,747 H4.7
PB0: P7.8 P22.8 R78.2 R80.2 | length 552.6
  Top Layer w20: R78.2 1611,2111.62 P7.8 P22.8
  Bottom Layer w20: R80.2 1611,2111.62 P7.8
PB0_24: H8.8 U3.21 | length 582.5
  Top Layer w10: U3.21 3291.85,2010.94 H8.8
PB0_32: H4.8 U1.25 | length 611.9
  Top Layer w10: U1.25 3334.1,672.1 3350,688 3475,688 3569,782 H4.8
PB1: P6.1 P11.3 P21.1 R49.2 R51.2 | length 1354.6
  Top Layer w20: R49.2 1754.11,1992 P6.1 ; P21.1 P6.1 ; P11.3 1911,2593 1829.11,2511.11 P6.1
  Bottom Layer w20: R51.2 1754.11,1992 P6.1
PB1_20: H11.1 U4.17 | length 760.5
  Top Layer w12: U4.17 3302.52,3242.52 3423,3363 H11.1
PB1_24: H7.1 U3.20 | length 690.7
  Top Layer w10: U3.20 3307.6,1933.6 3544,2170 H7.1
PB1_32: H3.1 U1.24 | length 592.9
  Top Layer w10: U1.24 3474.29,630.29 3664,820 3664,853.89 H3.1
PB1_RX: P4.3 P11.4 R1.1 RX.1 | length 1227
  Top Layer w20: P11.4 2129,2237 2205,2161 2205,1906 2254.96,1856.04 R1.1 2487.96,1856.04 P4.3
  Bottom Layer w20: RX.1 2373,1796 2428,1851 P4.3
PB2: C12.2 P6.2 P21.2 R11.2 R53.2 R55.2 S2.1 | length 2310.8
  Top Layer w10: R11.2 C12.2 ; S2.1 S2.1 C12.2 ; v2(1881,684) 1861.96,664.96 C12.2
  Top Layer w20: R53.2 1763.54,1901.43 P6.2 P21.2
  Bottom Layer w10: v2(1881,684) 1998,801 1998,1860.3 P21.2
  Bottom Layer w20: R55.2 1763.54,1901.43 P6.2
PB2_20: H11.2 U4.16 | length 564.8
  Top Layer w12: U4.16 3573.64,3263 H11.2
PB2_24: H7.2 U3.19 | length 560.8
  Top Layer w10: U3.19 3577.94,2070 H7.2
PB2_32: H3.2 U1.23 | length 538.1
  Top Layer w10: U1.23 3524.65,614.54 H3.2
PB3: P6.3 P21.3 R57.2 R59.2 | length 561
  Top Layer w20: R57.2 1772.97,1810.86 P6.3 P21.3
  Bottom Layer w20: R59.2 1772.97,1810.86 P6.3
PB3_20: H11.3 U4.15 | length 530.8
  Top Layer w12: U4.15 3413.87,2991.87 3585,3163 H11.3
PB3_32: H3.3 U1.22 | length 503.2
  Top Layer w10: U1.22 3608.9,598.79 H3.3
PB4: P6.4 P21.4 R61.2 R63.2 | length 553.2
  Top Layer w20: R61.2 1782.4,1720.29 P6.4 P21.4
  Bottom Layer w20: R63.2 1782.4,1720.29 P6.4
PB4_24: H7.4 U3.18 | length 487.9
  Top Layer w10: U3.18 3398.66,1799.66 3469,1870 H7.4
PB4_32: H3.4 U1.21 | length 468.3
  Top Layer w10: U1.21 3693.15,583.04 H3.4
PB5: P6.5 P21.5 R65.2 R67.2 | length 545.4
  Top Layer w20: R65.2 1791.82,1629.71 P6.5 P21.5
  Bottom Layer w20: R67.2 1791.82,1629.71 P6.5
PB5_24: H7.5 U3.17 | length 464.6
  Top Layer w10: U3.17 3329.06,1783.17 3569.83,1783.17 3583,1770 H7.5
PB5_32: H3.5 U1.20 | length 433.4
  Top Layer w10: U1.20 3777.41,567.3 H3.5
PB6: CS.1 P6.6 P21.6 R69.2 R71.2 U2.1 | length 3052.6
  Top Layer w10: U2.1 814,2453 834,2473 v2(834,2545)
  Top Layer w20: CS.1 752.86,2242.86 U2.1 ; R69.2 1801.25,1539.14 P6.6 P21.6
  Bottom Layer w10: v2(834,2545) 834,2568 853,2587 1823,2587 1941,2469 1941,1678.89 P6.6
  Bottom Layer w20: R71.2 1801.25,1539.14 P6.6
PB6_24: H7.6 U3.16 | length 499.5
  Top Layer w10: U3.16 3476.83,1768.17 3575,1670 H7.6
PB6_32: H3.6 U1.19 | length 460.3
  Top Layer w10: U1.19 3532.45,551.55 3607,477 H3.6
PB7: P6.7 P21.7 R73.2 R75.2 | length 529.8
  Top Layer w20: R73.2 1810.68,1448.57 P6.7 P21.7
  Bottom Layer w20: R75.2 1810.68,1448.57 P6.7
PB7_20: H11.7 U4.14 | length 546.6
  Top Layer w12: U4.14 3482.81,2972.19 3692,2763 H11.7
PB7_32: H3.7 U1.18 | length 495.2
  Top Layer w10: U1.18 3465.2,535.8 3624,377 H3.7
PC0: P6.8 P21.8 R77.2 R79.2 | length 522
  Top Layer w20: R77.2 1718.64,1367 P6.8 P21.8
  Bottom Layer w20: R79.2 1718.64,1367 P6.8
PC0_24: H7.8 U3.14 | length 569.3
  Top Layer w10: U3.14 3450.33,1736.67 3717,1470 H7.8
PC0_32: H3.8 U1.17 | length 530.1
  Top Layer w10: U1.17 3408.95,520.05 3652,277 H3.8
PC1: AD14.1 C13.2 P2.8 P20.8 R16.1 R46.2 R48.2 | length 2208.4
  Top Layer w20: C13.2 820,210 903,127 AD14.1 ; R46.2 1568.86,1191.05 P20.8 P2.8
  Bottom Layer w20: AD14.1 1538,127 1611,200 P2.8 ; R48.2 1568.86,1191.05 P20.8
PC1_20: H10.8 U4.13 | length 648.4
  Top Layer w12: U4.13 3396.5,2952.5 3569,2780 H10.8
PC1_24: H6.8 U3.13 | length 562.3
  Top Layer w10: U3.13 3569,1475.27 H6.8
PC1_32: H2.8 U1.16 | length 534.7
  Top Layer w10: U1.16 3334.09,476.91 3569,242 H2.8
PC2: P2.7 P20.7 R42.2 R44.2 | length 543.4
  Top Layer w20: R42.2 1476.14,1183.76 P20.7 P2.7
  Bottom Layer w20: R44.2 1476.14,1183.76 P20.7
PC2_24: H6.7 U3.12 | length 530.9
  Top Layer w10: U3.12 3307.6,1638.4 3469,1477 H6.7
PC2_32: H2.7 U1.15 | length 499.8
  Top Layer w10: U1.15 3318.34,389.66 3469,239 H2.7
PC3: P2.6 P20.6 R38.2 R40.2 | length 537.4
  Top Layer w20: R38.2 1383.43,1176.48 P20.6 P2.6
  Bottom Layer w20: R40.2 1383.43,1176.48 P20.6
PC3_24: H6.6 U3.11 | length 496
  Top Layer w10: U3.11 3291.85,1545.15 3369,1468 H6.6
PC3_32: H2.6 U1.14 | length 464.9
  Top Layer w10: U1.14 3302.59,308.41 3369,242 H2.6
PC4: P2.5 P20.5 R34.2 R36.2 | length 531.4
  Top Layer w20: R34.2 1290.71,1169.19 P20.5 P2.5
  Bottom Layer w20: R36.2 1290.71,1169.19 P20.5
PC4_32: H2.5 U1.13 | length 444.7
  Top Layer w10: H2.5 3269,228 3286.84,245.84 U1.13
PC5: P2.4 P20.4 R30.2 R32.2 | length 525.3
  Top Layer w20: R30.2 1198,1161.91 P20.4 P2.4
  Bottom Layer w20: R32.2 1198,1161.91 P20.4
PC5_32: H2.4 U1.12 | length 479.6
  Top Layer w10: H2.4 3169,195 3271.09,297.09 U1.12
PC6: P2.3 P20.3 R27.2 R28.2 | length 519.3
  Top Layer w20: R27.2 1105.29,1154.62 P20.3 P2.3
  Bottom Layer w20: R28.2 1105.29,1154.62 P20.3
PC6_20: H10.3 U4.11 | length 663.9
  Top Layer w12: H10.3 3069,2486 3105,2522 3263,2522 3325.19,2584.19 U4.11
PC6_32: H2.3 U1.11 | length 514.5
  Top Layer w10: H2.3 3069,155 3255.35,341.35 U1.11
PD0: C5.2 P2.2 P9.1 P20.2 R5.2 R25.2 R26.2 | length 2460.7
  Top Layer w20: R25.2 1011,1266.82 P20.2 P2.2 1011,808 1038,781 2179,781 2261.92,698.08 C5.2 2261.92,115.08 P9.1
  Bottom Layer w20: P20.2 1011,1266.82 R26.2
PD0_20: H10.2 U4.10 | length 712.1
  Top Layer w12: H10.2 2979.57,2455.47 2979.57,2507.57 3034,2562 3223,2562 3302.52,2641.52 U4.10
PD0_24: H6.2 U3.10 | length 591.3
  Top Layer w10: H6.2 2969,1306 3276.1,1613.1 U3.10
PD0_32: H2.2 U1.10 | length 549.4
  Top Layer w10: H2.2 2969,131 3239.6,401.6 U1.10
PD1: C18.2 P2.1 P9.2 P20.1 R6.2 R22.2 R24.2 | length 2448.1
  Top Layer w20: R22.2 911,1259.54 P20.1 P2.1 911,795 973,733 2082,733 2162.04,652.96 R6.2 C18.2 P9.2 P9.2
  Bottom Layer w20: P20.1 911,1259.54 R24.2
PD1_20: H10.1 U4.9 | length 781.1
  Top Layer w12: H10.1 2869,2539 2939,2609 3189,2609 3282.84,2702.84 U4.9
PD1_24: H6.1 U3.9 | length 626.2
  Top Layer w10: H6.1 3260.35,1643.26 U3.9
PD1_32: H2.1 U1.9 | length 584.3
  Top Layer w10: H2.1 2869,104 3223.85,458.85 U1.9
PD2: C10.2 P1.8 P19.8 R8.2 R45.2 R47.2 S1.1 | length 1850.7
  Top Layer w10: v2(1002,589) 1030,561 R8.2 C10.2 S1.1 S1.1
  Top Layer w20: P1.8 P19.8 836.35,1367 R45.2
  Bottom Layer w10: P19.8 721,1295.12 721,871 1002,590 v2(1002,589)
  Bottom Layer w20: P19.8 836.35,1367 R47.2
PD2_20: H9.8 U4.8 | length 705.8
  Top Layer w12: H9.8 3175,2663 3263.15,2751.15 U4.8
PD2_24: H5.8 U3.8 | length 614.5
  Top Layer w10: H5.8 3031,1470 3244.61,1683.61 U3.8
PD2_32: H1.8 U1.8 | length 567.5
  Top Layer w10: H1.8 2987,277 3200.24,490.24 U1.8
PD3: C15.2 P1.7 P19.7 R19.2 R41.2 R43.2 S3.1 | length 2456
  Top Layer w10: v2(1360,539) 1382,561 R19.2 C15.2 S3.1 S3.1
  Top Layer w20: P1.7 P19.7 845.35,1467 R41.2
  Bottom Layer w10: P19.7 636,1310.12 636,802 899,539 v2(1360,539)
  Bottom Layer w20: P19.7 845.35,1467 R43.2
PD3_20: H9.7 U4.7 | length 609.9
  Top Layer w12: H9.7 3196,2763 3243.47,2810.47 U4.7
PD3_24: H5.7 U3.7 | length 532
  Top Layer w10: H5.7 3077.94,1570 U3.7
PD3_32: H1.7 U1.7 | length 551.6
  Top Layer w10: H1.7 2794.88,333 2987,333 3189.8,535.8 U1.7
PD4: P1.6 P19.6 R37.2 R39.2 | length 562.6
  Top Layer w20: P1.6 P19.6 854.35,1567 R37.2
  Bottom Layer w20: P19.6 854.35,1567 R39.2
PD4_32: H1.6 U1.6 | length 539.9
  Top Layer w10: H1.6 2822.88,405 3021,405 3167.55,551.55 U1.6
PD5: P1.5 P5.2 P19.5 R33.2 R35.2 | length 1065.6
  Top Layer w20: P5.2 207,1430 444,1667 P1.5 P19.5 863.35,1667 R33.2
  Bottom Layer w20: P19.5 863.35,1667 R35.2
PD5_20: H9.5 U4.6 | length 573.1
  Top Layer w12: H9.5 2901.88,2812 3122.65,2812 U4.6
PD5_24: H5.5 U3.6 | length 577.7
  Top Layer w10: H5.5 2893.88,1627 3092,1627 3201.67,1736.67 U3.6
PD5_32: H1.5 U1.5 | length 543.1
  Top Layer w10: H1.5 2868.88,459 3039,459 3147.3,567.3 U1.5
PD6: P1.4 P5.3 P19.4 R29.2 R31.2 | length 1058.1
  Top Layer w20: P5.3 197,1530 434,1767 P1.4 P19.4 872.35,1767 R29.2
  Bottom Layer w20: P19.4 872.35,1767 R31.2
PD6_20: H9.4 U4.5 | length 586.3
  Top Layer w12: H9.4 2958.88,2855 3104,2855 3181.82,2932.82 U4.5
PD6_24: H5.4 U3.5 | length 596
  Top Layer w10: H5.4 2957.88,1663 3091.95,1663 3181.37,1752.42 3202.37,1752.42 3202.6,1752.18 3223.65,1752.18 U3.5
PD6_32: H1.4 U1.4 | length 552.1
  Top Layer w10: H1.4 2921.88,506 3050,506 3127.04,583.04 U1.4
VCC: C8.2 C9.2 C19.2 P1.2 P1.3 P4.1 P5.1 P15.1 P15.2 P15.3 P16.1 P16.2 P16.3 P19.2 P19.3 P31.1 P31.2 P31.3 P32.1 P32.2 P32.3 R1.2 R2.2 R3.2 R4.2 R8.1 R9.2 R10.2 R11.1 R12.1 R18.2 R19.1 R20.2 R21.1 R22.1 R25.1 R27.1 R29.1 R30.1 R33.1 R34.1 R37.1 R38.1 R41.1 R42.1 R45.1 R46.1 R49.1 R50.1 R53.1 R54.1 R57.1 R58.1 R61.1 R62.1 R65.1 R66.1 R69.1 R70.1 R73.1 R74.1 R77.1 R78.1 R81.2 U2.3 U2.7 U2.8 VCC.1 VR1.2 | length 5843
  Top Layer w15: R4.2 456.33,1927.96 P1.3 ; R3.2 314.21,2170.08 P1.2 ; R22.1 R25.1 ; R50.1 R54.1 R58.1 R62.1 R66.1 R70.1 R74.1 R78.1 1636.02,2004.99 R49.1 R53.1 R57.1 R61.1 R65.1 R69.1 R73.1 R77.1 1620.03,1329.02 R46.1 R42.1 R38.1 R34.1 R30.1 R27.1 R25.1 ; R21.1 R29.1 R33.1 R37.1 R41.1 R45.1 972.98,1368.61 R25.1 ; R2.2 2404.96,2051 P4.1 ; R1.2 2374,1801 2538,1801 2566,1829 2566,2038 2565,2039
  Top Layer w40: 508,2478 393,2478 360,2511 360,2641 404,2685 C19.2 580.96,2648.04 676,2553 U2.3 U2.3@780,2553 ; VR1.2@1562.89,3196 VR1.2@1799.11,3196 ; VCC.1 1799.11,3438.11 VR1.2@1799.11,3196 ; P16.3@2058,3441 P16.3@2060,3441 ; P16.3 P16.3@2060,3441 ; P16.1@2260,3441 P16.3@2060,3441 ; VR1.2@1799.11,3196 2056.57,3196 C9.2 P16.3@2060,3441
VCC_20: C11.2 H9.2 H9.3 U4.4 | length 675.4
  Top Layer w15: C11.2 3112.54,2952.5 U4.4
  Top Layer w40: H9.2 H9.3 2985.92,2927.96 C11.2
VCC_24: C4.2 H5.2 H5.3 U3.4 | length 685.9
  Top Layer w10: 3131.96,1732.96 3167.42,1768.42 U3.4@3223.89,1768.42
  Top Layer w12: C4.2 3131.96,1732.96
  Top Layer w40: H5.2 H5.3 2987.92,1732.96 C4.2
VCC_32: C1.2 H1.2 H1.3 U1.2 U1.3 | length 638.3
  Top Layer w25: C1.2@3048.96,584.96 3071.67,607.67 3200.24,607.67
  Top Layer w30: C1.2 C1.2@3048.96,584.96
  Top Layer w40: H1.2 H1.3 2942.92,584.96 C1.2
VDD1: C6.2 C7.2 POWER.2 POWER.5 VR1.3 | length 747
  Top Layer w40: POWER.2 POWER.5 1114.77,3267.23 1252.65,3129.35 C7.2 C6.2 1427.91,3105.45 VR1.3
pads on no net: H5.6 H6.3 H6.4 H6.5 H7.3 H7.7 H8.5 H8.6 H8.7 H9.6 H10.4 H10.5 H10.6 H10.7 H11.4 H11.5 H11.6 H11.8 H12.5 H12.6 H12.7 H12.8 P36.2 P36.3 P36.4 POWER.3 POWER.6
copper on no net:
  other v3: 106,106 2522,106 106,3431 2522,3431

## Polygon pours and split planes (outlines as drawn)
GND_32 on Bottom Layer "Top Layer-No Net" (solid, remove dead copper, pour order 18): 2695,1170 3850,1170 3850,-5 2695,-5
GND_24 on Bottom Layer "Top Layer-No Net" (solid, remove dead copper, pour order 16): 3850,2365 2696.47,2365 2696.47,1185.47 2696,1185 3850,1185
GND_20 on Bottom Layer "Top Layer-No Net" (solid, remove dead copper, pour order 14): 2695,3540 3850,3540 3850,2365 2695,2365
GND on Bottom Layer "Top Layer-No Net" (solid, remove dead copper, pour order 4): -5,3540 2675,3540 2675,-5 -5,-5
GND_32 on Top Layer "Top Layer-No Net" (solid, remove dead copper, pour order 12): 2695,1170 3850,1170 3850,-5 2695,-5
GND_24 on Top Layer "Top Layer-No Net" (solid, remove dead copper, pour order 10): 2696.47,2365 3850,2365 3850,1185 2696,1185
GND_20 on Top Layer "Top Layer-No Net" (solid, remove dead copper, pour order 8): 2695,3540 3850,3540 3850,2365 2695,2365
GND on Top Layer "Top Layer-No Net" (solid, remove dead copper, pour order 6): -5,3540 2675,3540 2675,-5 -5,-5

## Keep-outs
Keep-Out Layer:
  lines w3.94: 0,104 0,3431 cw(c106,3431) 106,3537 3741,3537 cw(c3741,3431) 3847,3431 3847,105 ; 0,106 ccw(c106,106) 106,0 ; 104,0 3742,0 ; 3741,0 ccw(c3741,106) 3847,106

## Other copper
Top Layer:
  rectangle net GND_20: 3209,2967 3273,2977
  rectangle net GND_32: 3197,934 3320,987
  rectangle net GND: 378.35,3019.12 440,3070
  rectangle net GND: 294,2986 472,3032
  rectangle net GND: 1271,3255 1614,3305
  rectangle net GND: 1271,3175 1437,3305
  rectangle net VCC: 464,619 1809,655
  rectangle net VCC: 403,227 495,987
  rectangle net VCC: 84,894 480,987
  rectangle net VCC: 75,894 180,1178
  rectangle net VCC: 2462,2017 2575,2884
  rectangle net VCC: 2172,2797 2572,2884
  rectangle net VCC: 755,1840 824,1897
  rectangle net VCC: 755,1839 991,1866
  rectangle net VCC: 438,2436 531,2522
  rectangle net VCC: 557,2657 603,2795
  rectangle net NetD7_A: 252,2531 309,2667
  rectangle net VCC: 250,2692 310,2784
  rectangle net VCC: 19,2467 156,2837
  rectangle net VCC: 56,2766 841,2837
  rectangle net VCC: 770,2766 841,2987
  rectangle net VCC: 770,2913 2267,2987
  rectangle net VCC: 2172,2797 2270,3265
  rectangle net VCC: 1758,3174 2270,3265
Bottom Layer:
  rectangle net VCC: 362,1823 830,2003
  rectangle net VCC: 362,1646 450,2003
  rectangle net VCC: 181,1614 450,1707
  rectangle net VCC: 75,895 214,1362
  rectangle net VCC: 148,895 214,2287
  rectangle net VCC: 35,2233 215,2313
  rectangle net VCC: 35,2233 140,2780

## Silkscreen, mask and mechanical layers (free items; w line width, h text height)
Top Overlay:
  region: 2725.5,1047.5 2801,1123 2801,1047 2800.5,1047.5
  region: 2724.5,2240.5 2800,2316 2800,2240 2799.5,2240.5
  region: 2724.5,3433.5 2800,3509 2800,3433 2799.5,3433.5
  region: 767.5,2138.5 843,2214 843,2138 842.5,2138.5
  lines w3.94: 767.5,2138 843,2138 843,2214 767.5,2138.5 ; 2725.5,1048 2801,1048 2801,1124 2725.5,1048.5 ; 2725.5,2241 2801,2241 2801,2317 2725.5,2241.5 ; 2725.5,3434 2801,3434 2801,3510 2725.5,3434.5
  lines w7.87: 1883,3028 1895,3016 1895,2279
  lines w8: 0,569 355,569 467,681 467,752 467,1217 2,1217 ; 3,1726 467.29,1726 ; 4,2386 31,2386 369,2386 ; 406,2196 371,2196 369,2198 369,2386 ; 467.29,2117 467.29,2195.71 ; 468,681 859,681 ; 469,2196 786,2196 825.09,2235.09 861,2271 861,2410.68 ; 857,2788 453,2788 369,2704 369,2386 ; 861,823.31 861,678 1040,499 1040,3 ; 861,2510.68 861,2932 861,3015 ; 863,3017 874,3028 1883,3028 ; 1761,823.31 2032.69,823.31 2033,823 ; 1894,3009 2274,3009 2449,2834 2449,2270 ; 1895,2279 1905,2269 2241,2269 2656,2269 ; 1952,4 1952,123 ; 1952,402 2656,402 ; 2033,403 2033,823 ; 2033,754 2033,823 ; 2154.7,1217 2154.7,944.7 2033,823 ; 2154.7,2117 2154.7,2267 ; 2156,1500 2625,1500 2654,1500 ; 1112,1441 1515,1441 1515,1902 1515,1916 1112,1916 1112,1441
  lines w10: -5,-41 -5,-21 ; 55,-51 -5,-31 ; 55,-11 -5,-31 ; 1051.09,-31 -5,-31 ; 1612.91,-31 2669,-31 ; 2609,-51 2669,-31 ; 2609,-11 2669,-31 ; 2669,-41 2669,-21 ; 2694,-42 2694,-22 ; 2754,-52 2694,-32 ; 2754,-12 2694,-32 ; 2999.58,-32 2694,-32 ; 3541.42,-32 3847,-32 ; 3787,-52 3847,-32 ; 3787,-12 3847,-32 ; 3847,-42 3847,-22 ; 3874.02,3475 3894,3535 ; 3874.98,63 3895,3 ; 3884,3535 3904,3535.01 ; 3885,3 3905,3.01 ; 3894.42,2049.92 3894,3535 ; 3894.58,1488.09 3895,3 ; 3914.02,3475.01 3894,3535 ; 3914.98,63.01 3895,3
  text "3005_DEMO_V100" at 276,3490 h32
  text "20200909" at 348,3436 h32
  text "G" at 3658,3419 h32 r270
  text "A1" at 2849,3388 h32
  text "A2" at 2946,3388 h32
  text "A3" at 3047,3387 h32
  text "A4" at 3144,3387 h32
  text "B1" at 3670,3340 h32
  text "A0" at 2813,3337 h32
  text "GND" at 1242,3316 h60
  text "VCC" at 2061,3310 h60
  text "VCC" at 2817,3246.12 h32
  text "B2" at 3670,3240 h32
  text "VCC=3.3V" at 2168,3204 h60
  text "VCC" at 2817,3146.25 h32
  text "B3" at 3670,3140 h32
  text "5V" at 457,3072 h60
  text "D6" at 2817,3046.38 h32
  text "D5" at 2817,2946.5 h32
  text "GND" at 2432,2864 h60
  text "PA1" at 970,2814 h32
  text "PA2" at 1246.89,2814 h32
  text "PA3" at 1523.78,2814 h32
  text "PA4" at 1800.67,2814 h32
  text "UART_SET" at 1934,2757 h60
  text "B7" at 3670,2748 h32
  text "D3" at 2817,2746.75 h32
  text "SPI" at 704,2711 h60
  text "VCC" at 151,2709 h60 r270
  text "20 PIN" at 3128,2675 h60
  text "D2" at 2817,2646.88 h32
  text "PA2" at 994.88,2608 h32 r270
  text "PA3" at 1094.75,2608 h32 r270
  text "PA4" at 1194.62,2608 h32 r270
  text "PA5" at 1294.5,2608 h32 r270
  text "PA6" at 1394.38,2608 h32 r270
  text "PA7" at 1494.25,2608 h32 r270
  text "PB0" at 1594.12,2608 h32 r270
  text "GND" at 1694,2608 h32 r270
  text "PA1" at 895,2597.34 h32 r270
  text "PB1" at 1992,2578 h32
  text "PA4" at 2293,2578 h32
  text "G" at 2816,2546 h32
  text "G" at 3704,2546 h32
  text "VCC" at 2593,2538 h60 r270
  text "D1" at 2850,2507 h32
  text "D0" at 2944,2507 h32
  text "C6" at 3044,2507 h32
  text "C1" at 3548,2507 h32
  text "G" at 3656,2507 h32
  text "RX" at 2013.33,2475 h32
  text "TX" at 2293,2475 h32
  text "IIC" at 16,2371 h60 r270
  text "32" at 886,2287 h32
  text "31" at 991,2287 h32
  text "30" at 1085,2287 h32
  text "29" at 1186,2287 h32
  text "28" at 1287,2287 h32
  text "27" at 1385,2287 h32
  text "26" at 1487,2287 h32
  text "25" at 1586,2287 h32
  text "G" at 1699,2287 h32
  text "G" at 3658,2225 h32 r270
  text "GND" at 10,2203 h32 r270
  text "A1" at 2850,2195 h32
  text "A2" at 2942,2195 h32
  text "A4" at 3144,2195 h32
  text "B0" at 3544,2195 h32
  text "A3" at 3044,2194 h32
  text "B1" at 3683,2155 h32
  text "A0" at 2813,2144 h32
  text "SCL" at 10,2091 h32 r270
  text "B2" at 3672,2056 h32
  text "24" at 1931,2052 h32
  text "VCC" at 2820,2052.12 h32
  text "PA0" at 370,2051 h32
  text "1" at 680.66,2050 h32
  text "PB1" at 2166,2049 h32
  text "3532 (mil)" at 3858.43,2039.91 h60 r270.02
  text "VCC" at 2555,2038 h32
  text "B1" at 1658,2035 h32
  text "A1" at 865,2019 h32
  text "SDA" at 10,1984 h32 r270
  text "23" at 1931,1952.12 h32
  text "VCC" at 2820,1952.25 h32
  text "VCC" at 370,1951.12 h32
  text "2" at 670,1950.12 h32
  text "PB2" at 2166,1949 h32
  text "TXD" at 2555,1936 h32
  text "A2" at 1012,1931 h32
  text "A3" at 1099.67,1931 h32
  text "A4" at 1187.33,1931 h32
  text "A5" at 1275,1931 h32
  text "A6" at 1362.67,1931 h32
  text "A7" at 1450.33,1931 h32
  text "B0" at 1538,1931 h32
  text "B2" at 1554,1884 h32
  text "A0" at 1015,1882 h32
  text "B4" at 3672,1854 h32
  text "22" at 1931,1852.25 h32
  text "D6" at 2820,1852.38 h32
  text "VCC" at 370,1851.25 h32
  text "3" at 670,1850.25 h32
  text "PB3" at 2166,1849 h32
  text "RXD" at 2555,1837 h32
  text "B3" at 1554,1793.6 h32
  text "D6" at 1015,1790.6 h32
  text "B5" at 3671,1754 h32
  text "21" at 1931,1752.38 h32
  text "D5" at 2820,1752.5 h32
  text "PD6" at 370,1751.38 h32
  text "4" at 670,1750.38 h32
  text "PB4" at 2166,1749 h32
  text "GND" at 2555,1736 h32
  text "B4" at 1554,1703.2 h32
  text "D5" at 1015,1699.2 h32
  text "GND" at 10,1681 h32 r270
  text "Pull-up res" at 1140,1668 h32
  text "B6" at 3672,1655 h32
  text "PD5" at 370,1651.5 h32
  text "20" at 1931,1652.5 h32
  text "5" at 670,1650.5 h32
  text "PB5" at 2166,1649 h32
  text "B5" at 1553,1612.8 h32
  text "D4" at 1015,1607.8 h32
  text "SWD" at 217,1583 h60 r270
  text "DIO" at 10,1567.67 h32 r270
  text "19" at 1931,1552.62 h32
  text "D3" at 2820,1552.75 h32
  text "PD4" at 370,1551.62 h32
  text "6" at 670,1550.62 h32
  text "PB6" at 2166,1549 h32
  text "B6" at 1553,1522.4 h32
  text "UART" at 2329,1519 h60
  text "D3" at 1015,1516.4 h32
  text "24 PIN" at 3131,1492 h60
  text "CLK" at 10,1465 h32 r270
  text "18" at 1931,1452.75 h32
  text "D2" at 2820,1452.88 h32
  text "PD3" at 370,1451.75 h32
  text "7" at 670,1450.75 h32
  text "C0" at 3671,1451 h32
  text "PB7" at 2166,1449 h32
  text "B7" at 1554,1432 h32
  text "D2" at 1015,1425 h32
  text "D1" at 898,1369 h32
  text "D0" at 986,1369 h32
  text "C6" at 1079,1369 h32
  text "C5" at 1170,1369 h32
  text "C4" at 1264,1369 h32
  text "C3" at 1357,1369 h32
  text "C2" at 1449,1369 h32
  text "C1" at 1545,1369 h32
  text "VCC" at 10,1357 h32 r270
  text "17" at 1931,1352.88 h32
  text "PD2" at 370,1351.88 h32
  text "G" at 2819,1352 h32
  text "8" at 670,1350.88 h32
  text "G" at 3711,1351 h32
  text "PC0" at 2166,1349 h32
  text "D1" at 2848,1314 h32
  text "D0" at 2945,1314 h32
  text "C3" at 3344,1314 h32
  text "C2" at 3443,1314 h32
  text "C1" at 3547,1314 h32
  text "G" at 3658,1314 h32
  text "C0" at 1654,1283 h32
  text "G" at 1931,1253 h32
  text "GND" at 370,1252 h32
  text "G" at 670,1251 h32
  text "GND" at 2166,1249 h32
  text "GND" at 2431,1179 h60
  text "VCC" at 189,1116 h60 r270
  text "G" at 3662,1039.99 h32 r270
  text "9" at 898,1015 h32
  text "10" at 986,1015 h32
  text "11" at 1091,1015 h32
  text "12" at 1187,1015 h32
  text "13" at 1287,1015 h32
  text "14" at 1386,1015 h32
  text "15" at 1486,1015 h32
  text "16" at 1587,1015 h32
  text "G" at 1699,1015 h32
  text "A1" at 2850,1001 h32
  text "A2" at 2949.43,1001 h32
  text "A3" at 3048.86,1001 h32
  text "A4" at 3148.29,1001 h32
  text "A5" at 3247.71,1001 h32
  text "A6" at 3347.14,1001 h32
  text "A7" at 3446.57,1001 h32
  text "B0" at 3546,1001 h32
  text "B1" at 3667,958 h32
  text "A0" at 2814,957 h32
  text "B2" at 3667,858 h32
  text "VCC" at 2814,857.12 h32
  text "GND" at 2432,831 h60
  text "PD1" at 896,812 h32 r270
  text "PD0" at 996.12,812 h32 r270
  text "PC6" at 1096.25,812 h32 r270
  text "PC5" at 1196.38,812 h32 r270
  text "PC4" at 1296.5,812 h32 r270
  text "PC3" at 1396.62,812 h32 r270
  text "PC2" at 1496.75,812 h32 r270
  text "PC1" at 1596.88,812 h32 r270
  text "GND" at 1697,812 h32 r270
  text "GND" at 291,786 h60 r270
  text "B3" at 3667,758 h32
  text "VCC" at 2814,757.25 h32
  text "B4" at 3667,658 h32
  text "D6" at 2814,657.38 h32
  text "ADC" at 595,600 h60
  text "JLCJLCJLCJLC" at 2252,585 h32 r90
  text "D5" at 2814,557.5 h32
  text "B5" at 3667,558 h32
  text "GND" at 2432,475 h60
  text "D4" at 2814,457.62 h32
  text "B6" at 3667,458 h32
  text "D3" at 2814,357.75 h32
  text "B7" at 3667,358 h32
  text "DAC" at 2472,305 h60
  text "32 PIN" at 3134,282 h60
  text "D2" at 2814,257.88 h32
  text "C0" at 3667,258 h32
  text "G" at 3704,159 h32
  text "G" at 2813,157 h32
  text "D1" at 2848,121 h32
  text "D0" at 2944,121 h32
  text "C6" at 3040,121 h32
  text "C5" at 3143,121 h32
  text "C4" at 3243,121 h32
  text "C3" at 3342,121 h32
  text "C2" at 3442,121 h32
  text "C1" at 3549,121 h32
  text "G" at 3658,121 h32
  text "PC1" at 922,39 h32
  text "PD2" at 1153,22 h32
  text "PD3" at 1487.5,22 h32
  text "PB2" at 1822,22 h32
  text "GND" at 2018,21 h32
  text "PD1" at 2127,21 h32
  text "PD0" at 2230,21 h32
  text "2674 (mil)" at 1061.09,-66.99 h60
  text "1153 (mil)" at 3009.58,-67.99 h60
Bottom Overlay:
  lines w8: 1112,1441 1515,1441 1515,1916 1112,1916 1112,1441
  text "B1" at 1696,2035 h32
  text "A1" at 908,2020 h32
  text "A2" at 1066,1931 h32
  text "A3" at 1153,1931 h32
  text "A4" at 1239,1931 h32
  text "A5" at 1328,1931 h32
  text "A6" at 1416,1931 h32
  text "A7" at 1504,1931 h32
  text "B0" at 1591,1931 h32
  text "B2" at 1607,1884 h32
  text "A0" at 1068,1882 h32
  text "B3" at 1607,1793.6 h32
  text "D6" at 1068,1790.6 h32
  text "B4" at 1607,1703.2 h32
  text "D5" at 1068,1699.2 h32
  text "Pull-down res" at 1515,1666 h32
  text "B5" at 1608,1612.8 h32
  text "D4" at 1068,1607.8 h32
  text "B6" at 1608,1522.4 h32
  text "D3" at 1068,1516.4 h32
  text "B7" at 1607,1432 h32
  text "D2" at 1068,1425 h32
  text "D1" at 938.71,1369.98 h32
  text "D0" at 1041.7,1369.98 h32
  text "C6" at 1134.03,1369.98 h32
  text "C5" at 1226.36,1369.98 h32
  text "C4" at 1318.68,1369.98 h32
  text "C3" at 1411.01,1369.98 h32
  text "C2" at 1503.34,1369.98 h32
  text "C1" at 1585,1369 h32
  text "C0" at 1707,1283 h32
